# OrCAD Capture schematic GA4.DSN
size A
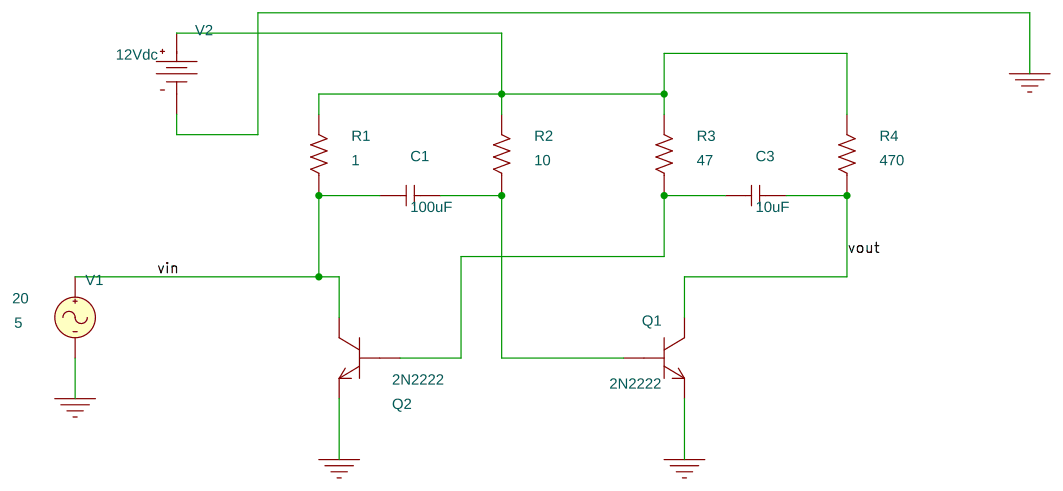
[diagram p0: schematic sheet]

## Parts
C1  100uF  [RAD/CK05]
C3  10uF  [RAD/CK05]
Q1  2N2222  [TO18]
Q2  2N2222  [TO18]
R1  1  [AX/RC05]
R2  10  [AX/RC05]
R3  47  [AX/RC05]
R4  470  [AX/RC05]
V1  VAC
V2  VDC

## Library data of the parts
C1 C3 = C
Q1 Q2 = 2N2222
R1-R4 = R
V1 = VAC: ACMAG: 20; DC: 5
V2 = VDC: DC: 12Vdc

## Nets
vin: C1.1 Q2.3(C) R1.1 V1.1(+)
0: Q1.1(E) Q2.1(E) V1.2(-) V2.1(-)
vout: C3.2 Q1.3(C) R4.1
N00305: R1.2 R2.2 R3.2 R4.2 V2.0(+)
N00333: C1.2 Q1.2(B) R2.1
N00337: C3.1 Q2.2(B) R3.1
